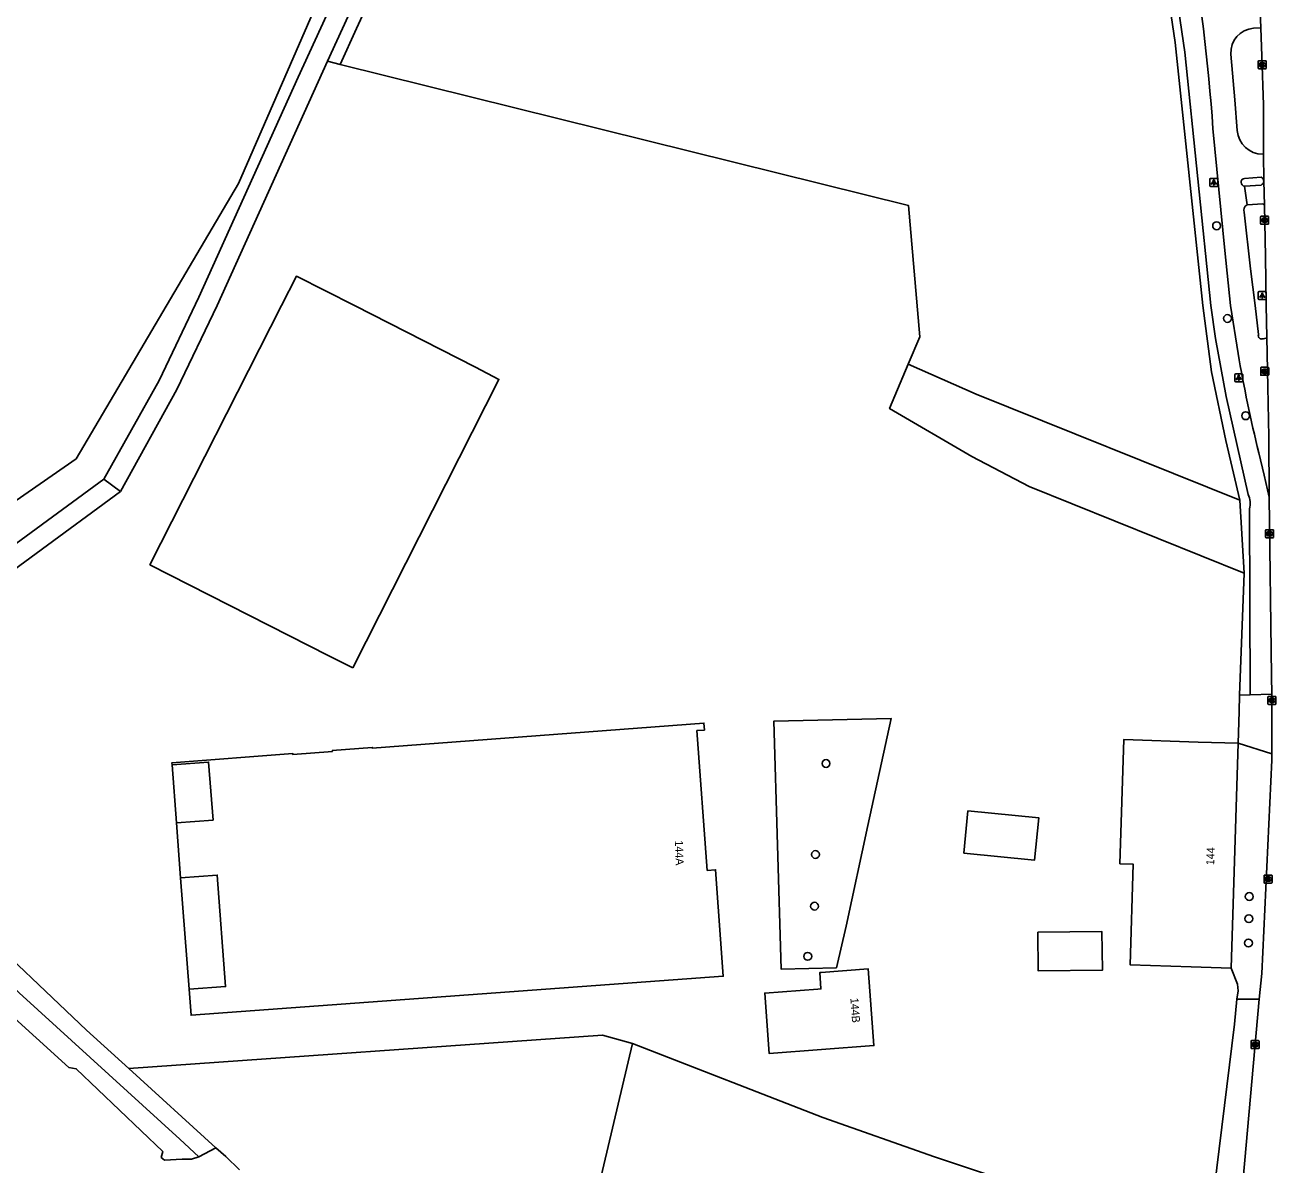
# Model space of a CAD drawing. Extents: x 160203 to 161526, y 379529 to 381797.
# Drawn here: x 160660 to 160816.2, y 380642.7 to 380785.1 of the extents above; entities that cross this region are included whole.
import ezdxf

# ---------------------------------------------------------------- set-up
doc = ezdxf.new("R2010")
doc.units = 0
for name, color, linetype in [('IMGEO_Boom', 7, 'Continuous'), ('IMGEO_Erf', 7, 'Continuous'), ('IMGEO_Grasland_agrarisch', 7, 'Continuous'), ('IMGEO_Groenvoorziening', 7, 'Continuous'), ('IMGEO_Hek', 7, 'Continuous'), ('IMGEO_Houtwal', 7, 'Continuous'), ('IMGEO_Kolk', 7, 'Continuous'), ('IMGEO_Lichtpunt', 7, 'Continuous'), ('IMGEO_Loofbos', 7, 'Continuous'), ('IMGEO_Pand', 7, 'Continuous'), ('IMGEO_Pand_nummerreeks', 7, 'Continuous'), ('IMGEO_Rijbaan_lokaal_gesloten', 7, 'Continuous'), ('IMGEO_Rijbaan_lokaal_open', 7, 'Continuous'), ('IMGEO_Voetpad_open', 7, 'Continuous')]:
    doc.layers.add(name, color=color, linetype=linetype)

msp = doc.modelspace()

# ---------------------------------------------------------------- linework, layer by layer
at = {"layer": 'IMGEO_Boom'}
for centre in [(160808.83, 380759.98), (160810.19, 380748.4), (160812.47, 380736.25), (160760.04, 380692.81), (160758.72, 380681.44), (160812.91, 380676.19), (160758.61, 380674.98), (160812.86, 380673.42), (160812.81, 380670.38), (160757.76, 380668.72)]:
    msp.add_circle(centre, 0.489, dxfattribs=at)
at = {"layer": 'IMGEO_Erf'}
for points in [[(160678.9, 380685.39), (160678.35, 380692.64)], [(160680.48, 380664.6), (160679.42, 380678.51)]]:
    msp.add_lwpolyline(points, dxfattribs=at)
at = {"layer": 'IMGEO_Grasland_agrarisch'}
for points in [[(160790.76, 380843.76), (160790.97, 380843.22), (160797.79, 380818.98), (160800.72, 380802.88), (160803.67, 380782.86), (160807.1, 380750), (160808.2, 380741.73), (160810, 380733.14), (160811.75, 380725.72)], [(160720.34, 380842.84), (160718.62, 380836.68), (160700.37, 380796.74), (160686.67, 380765.25), (160666.36, 380730.85), (160621.5, 380699.73)], [(160699.37, 380780.13), (160701.38, 380784.64), (160714.86, 380813.86), (160723.93, 380836.63), (160726.67, 380842.6)], [(160770.32, 380742.69), (160771.75, 380746.09), (160770.35, 380762.5), (160699.37, 380780.13)], [(160622.14, 380693.79), (160630.09, 380686.48), (160640.16, 380677.59), (160653.65, 380665.52), (160665.46, 380654.82), (160666.38, 380654.67), (160677.2, 380644.36), (160677, 380643.61), (160677.41, 380643.27), (160679.6, 380643.4), (160680.77, 380643.4), (160681.71, 380643.69)], [(160672.96, 380654.7), (160732.12, 380658.89), (160735.88, 380657.84)], [(160735.88, 380657.84), (160724.41, 380609.36)], [(160735.88, 380657.84), (160759.66, 380648.6), (160773.61, 380643.68), (160785.98, 380639.57), (160793.62, 380637.24), (160800.02, 380635.88), (160807.89, 380634.51)], [(160683.83, 380644.81), (160685.06, 380643.7), (160686.77, 380642.05)]]:
    msp.add_lwpolyline(points, dxfattribs=at)
at = {"layer": 'IMGEO_Groenvoorziening'}
for points in [[(160699.37, 380780.13), (160697.76, 380780.53)], [(160627.87, 380697.54), (160669.82, 380728.32)], [(160671.92, 380726.79), (160629.71, 380695.79)], [(160811.71, 380701.35), (160812.29, 380716.6)], [(160811.37, 380663.36), (160811.08, 380660.23), (160807.89, 380634.51)]]:
    msp.add_lwpolyline(points, dxfattribs=at)
at = {"layer": 'IMGEO_Hek'}
for points in [[(160724.66, 380842.65), (160726.67, 380842.6), (160727.3, 380842.58), (160755.37, 380841.81), (160764.5, 380841.73), (160790.97, 380843.22), (160797.79, 380818.98), (160800.72, 380802.88), (160803.67, 380782.86), (160807.1, 380750), (160808.2, 380741.73), (160810, 380733.14), (160811.75, 380725.72), (160812.29, 380716.6)], [(160697.76, 380780.53), (160717.43, 380823.37), (160724.66, 380842.65)], [(160671.92, 380726.79), (160669.82, 380728.32)], [(160762.54, 380672.48), (160761.33, 380667.29), (160754.45, 380667.1), (160753.51, 380698.09), (160768.19, 380698.42), (160765.28, 380685.05), (160762.54, 380672.48)]]:
    msp.add_lwpolyline(points, dxfattribs=at)
at = {"layer": 'IMGEO_Houtwal'}
for points in [[(160669.82, 380728.32), (160676.73, 380740.67), (160681.71, 380751.04), (160694.11, 380778.56), (160715.12, 380824.33), (160722.04, 380842.77)], [(160724.66, 380842.65), (160717.43, 380823.37), (160697.76, 380780.53)], [(160697.76, 380780.53), (160683.99, 380750), (160678.95, 380739.53), (160671.92, 380726.79)], [(160669.82, 380728.32), (160671.92, 380726.79)], [(160681.71, 380643.69), (160679.32, 380645.87), (160659.26, 380664.16), (160632.89, 380689.2), (160626.22, 380695.53), (160623.04, 380694.18), (160622.14, 380693.79)], [(160629.71, 380695.79), (160633.59, 380692.1), (160653.08, 380673.31), (160667.68, 380659.51), (160672.96, 380654.7)], [(160683.83, 380644.81), (160672.96, 380654.7)], [(160681.71, 380643.69), (160683.83, 380644.81)]]:
    msp.add_lwpolyline(points, dxfattribs=at)
at = {"layer": 'IMGEO_Kolk'}
for p, q in [((160814.03, 380779.66), (160814.03, 380780.51)), ((160814.1, 380780.59), (160814.95, 380780.59)), ((160815.03, 380780.51), (160815.03, 380779.66)), ((160814.95, 380779.58), (160814.1, 380779.58)), ((160814.51, 380780.36), (160814.54, 380780.36)), ((160814.54, 380779.81), (160814.51, 380779.81)), ((160814.33, 380760.25), (160814.33, 380761.1)), ((160814.4, 380761.18), (160815.26, 380761.18)), ((160815.26, 380760.18), (160814.4, 380760.18)), ((160814.84, 380760.4), (160814.81, 380760.4)), ((160814.82, 380760.96), (160814.84, 380760.96)), ((160815.33, 380761.1), (160815.33, 380760.25)), ((160814.34, 380741.37), (160814.34, 380742.22)), ((160814.41, 380742.3), (160815.26, 380742.3)), ((160814.82, 380742.08), (160814.85, 380742.08)), ((160814.85, 380741.52), (160814.82, 380741.52)), ((160815.34, 380742.22), (160815.34, 380741.37)), ((160815.26, 380741.3), (160814.41, 380741.3)), ((160814.94, 380721.08), (160814.94, 380721.93)), ((160815.02, 380722), (160815.87, 380722)), ((160815.43, 380721.78), (160815.46, 380721.78)), ((160815.45, 380721.22), (160815.43, 380721.22)), ((160815.94, 380721.93), (160815.94, 380721.08)), ((160815.87, 380721), (160815.02, 380721)), ((160815.25, 380700.27), (160815.25, 380701.12)), ((160815.32, 380701.19), (160816.18, 380701.19)), ((160815.74, 380700.97), (160815.76, 380700.97)), ((160816.25, 380701.12), (160816.25, 380700.27)), ((160816.18, 380700.19), (160815.32, 380700.19)), ((160815.76, 380700.41), (160815.73, 380700.41)), ((160814.84, 380678.87), (160815.69, 380678.87)), ((160814.77, 380677.95), (160814.77, 380678.8)), ((160815.69, 380677.87), (160814.84, 380677.87)), ((160815.25, 380678.65), (160815.28, 380678.65)), ((160815.28, 380678.09), (160815.25, 380678.09)), ((160815.77, 380678.8), (160815.77, 380677.95)), ((160813.14, 380657.27), (160813.14, 380658.13)), ((160813.22, 380658.2), (160814.07, 380658.2)), ((160814.07, 380657.2), (160813.22, 380657.2)), ((160813.63, 380657.98), (160813.65, 380657.98)), ((160813.65, 380657.42), (160813.63, 380657.42)), ((160814.14, 380658.13), (160814.14, 380657.27))]:
    msp.add_line(p, q, dxfattribs=at)
for points in [[(160814.03, 380779.66), (160814.03, 380780.51)], [(160814.1, 380780.59), (160814.95, 380780.59)], [(160815.03, 380780.51), (160815.03, 380779.66)], [(160814.95, 380779.58), (160814.1, 380779.58)], [(160814.35, 380780.28), (160814.47, 380780.28), (160814.47, 380780.13), (160814.6, 380780.28), (160814.76, 380780.28), (160814.62, 380780.13), (160814.77, 380779.88), (160814.62, 380779.88), (160814.53, 380780.05), (160814.47, 380779.98), (160814.47, 380779.88), (160814.35, 380779.88), (160814.35, 380780.28)], [(160814.33, 380760.25), (160814.33, 380761.1)], [(160814.4, 380761.18), (160815.26, 380761.18)], [(160815.26, 380760.18), (160814.4, 380760.18)], [(160814.65, 380760.88), (160814.77, 380760.88), (160814.77, 380760.72), (160814.9, 380760.88), (160815.07, 380760.88), (160814.92, 380760.73), (160815.07, 380760.48), (160814.92, 380760.48), (160814.84, 380760.64), (160814.77, 380760.57), (160814.77, 380760.48), (160814.65, 380760.48), (160814.65, 380760.88)], [(160815.33, 380761.1), (160815.33, 380760.25)], [(160814.34, 380741.37), (160814.34, 380742.22)], [(160814.41, 380742.3), (160815.26, 380742.3)], [(160814.66, 380742), (160814.78, 380742), (160814.78, 380741.85), (160814.91, 380742), (160815.07, 380742), (160814.93, 380741.85), (160815.08, 380741.6), (160814.93, 380741.6), (160814.84, 380741.76), (160814.78, 380741.69), (160814.78, 380741.6), (160814.66, 380741.6), (160814.66, 380742)], [(160815.34, 380742.22), (160815.34, 380741.37)], [(160815.26, 380741.3), (160814.41, 380741.3)], [(160814.94, 380721.08), (160814.94, 380721.93)], [(160815.02, 380722), (160815.87, 380722)], [(160815.26, 380721.7), (160815.39, 380721.7), (160815.39, 380721.55), (160815.52, 380721.7), (160815.68, 380721.7), (160815.54, 380721.55), (160815.69, 380721.3), (160815.54, 380721.3), (160815.45, 380721.47), (160815.39, 380721.4), (160815.39, 380721.3), (160815.26, 380721.3), (160815.26, 380721.7)], [(160815.94, 380721.93), (160815.94, 380721.08)], [(160815.87, 380721), (160815.02, 380721)], [(160815.25, 380700.27), (160815.25, 380701.12)], [(160815.32, 380701.19), (160816.18, 380701.19)], [(160815.57, 380700.89), (160815.69, 380700.89), (160815.69, 380700.74), (160815.82, 380700.89), (160815.99, 380700.89), (160815.84, 380700.74), (160815.99, 380700.49), (160815.84, 380700.49), (160815.76, 380700.66), (160815.69, 380700.59), (160815.69, 380700.49), (160815.57, 380700.49), (160815.57, 380700.89)], [(160816.25, 380701.12), (160816.25, 380700.27)], [(160816.18, 380700.19), (160815.32, 380700.19)], [(160814.84, 380678.87), (160815.69, 380678.87)], [(160814.77, 380677.95), (160814.77, 380678.8)], [(160815.69, 380677.87), (160814.84, 380677.87)], [(160815.09, 380678.57), (160815.21, 380678.57), (160815.21, 380678.42), (160815.34, 380678.57), (160815.5, 380678.57), (160815.36, 380678.42), (160815.51, 380678.17), (160815.36, 380678.17), (160815.27, 380678.34), (160815.21, 380678.27), (160815.21, 380678.17), (160815.09, 380678.17), (160815.09, 380678.57)], [(160815.77, 380678.8), (160815.77, 380677.95)], [(160813.14, 380657.27), (160813.14, 380658.13)], [(160813.22, 380658.2), (160814.07, 380658.2)], [(160814.07, 380657.2), (160813.22, 380657.2)], [(160813.46, 380657.9), (160813.59, 380657.9), (160813.59, 380657.75), (160813.71, 380657.9), (160813.88, 380657.9), (160813.73, 380657.75), (160813.89, 380657.5), (160813.73, 380657.5), (160813.65, 380657.67), (160813.59, 380657.6), (160813.59, 380657.5), (160813.46, 380657.5), (160813.46, 380657.9)], [(160814.14, 380658.13), (160814.14, 380657.27)]]:
    msp.add_lwpolyline(points, dxfattribs=at)
for centre, start, end in [((160814.1, 380780.51), 91.552, 178.448), ((160814.1, 380780.51), 91.552, 178.448), ((160814.95, 380780.51), 1.552, 88.448), ((160814.95, 380780.51), 1.552, 88.448), ((160814.1, 380779.66), 181.552, 268.448), ((160814.1, 380779.66), 181.552, 268.448), ((160814.95, 380779.66), 271.552, 358.448), ((160814.95, 380779.66), 271.552, 358.448), ((160814.41, 380761.1), 91.552, 178.448), ((160814.41, 380761.1), 91.552, 178.448), ((160814.41, 380760.25), 181.552, 268.448), ((160814.41, 380760.25), 181.552, 268.448), ((160815.25, 380761.1), 1.552, 88.448), ((160815.25, 380761.1), 1.552, 88.448), ((160815.25, 380760.25), 271.552, 358.448), ((160815.25, 380760.25), 271.552, 358.448), ((160814.41, 380742.22), 91.552, 178.448), ((160814.41, 380742.22), 91.552, 178.448), ((160814.41, 380741.37), 181.552, 268.448), ((160814.41, 380741.37), 181.552, 268.448), ((160815.26, 380742.22), 1.552, 88.448), ((160815.26, 380742.22), 1.552, 88.448), ((160815.26, 380741.37), 271.552, 358.448), ((160815.26, 380741.37), 271.552, 358.448), ((160815.02, 380721.93), 91.552, 178.448), ((160815.02, 380721.93), 91.552, 178.448), ((160815.02, 380721.08), 181.552, 268.448), ((160815.02, 380721.08), 181.552, 268.448), ((160815.87, 380721.93), 1.552, 88.448), ((160815.87, 380721.93), 1.552, 88.448), ((160815.87, 380721.08), 271.552, 358.448), ((160815.87, 380721.08), 271.552, 358.448), ((160815.32, 380701.12), 91.552, 178.448), ((160815.32, 380701.12), 91.552, 178.448), ((160816.17, 380701.12), 1.552, 88.448), ((160816.17, 380701.12), 1.552, 88.448), ((160815.32, 380700.27), 181.552, 268.448), ((160815.32, 380700.27), 181.552, 268.448), ((160816.17, 380700.27), 271.552, 358.448), ((160816.17, 380700.27), 271.552, 358.448), ((160814.84, 380678.8), 91.552, 178.448), ((160814.84, 380678.8), 91.552, 178.448), ((160815.69, 380678.8), 1.552, 88.448), ((160815.69, 380678.8), 1.552, 88.448), ((160814.84, 380677.95), 181.552, 268.448), ((160814.84, 380677.95), 181.552, 268.448), ((160815.69, 380677.95), 271.552, 358.448), ((160815.69, 380677.95), 271.552, 358.448), ((160813.22, 380658.13), 91.552, 178.448), ((160813.22, 380658.13), 91.552, 178.448), ((160813.22, 380657.28), 181.552, 268.448), ((160813.22, 380657.28), 181.552, 268.448), ((160814.07, 380658.13), 1.552, 88.448), ((160814.07, 380658.13), 1.552, 88.448), ((160814.07, 380657.28), 271.552, 358.448), ((160814.07, 380657.28), 271.552, 358.448)]:
    msp.add_arc(centre, 0.0765, start, end, dxfattribs=at)
for centre, major_axis, ratio, start_param, end_param in [((160814.51, 380780.08), (-0.387, 0.002), 0.722429, 4.712389, 7.853982), ((160814.54, 380780.08), (-0.39, 0.002), 0.717154, 1.570796, 4.712389), ((160814.82, 380760.68), (-0.387, 0.002), 0.722429, 4.712389, 7.853982), ((160814.84, 380760.68), (-0.39, 0.002), 0.717154, 1.570796, 4.712389), ((160814.82, 380741.8), (-0.387, 0.002), 0.722429, 4.712389, 7.853982), ((160814.85, 380741.8), (-0.39, 0.002), 0.717154, 1.570796, 4.712389), ((160815.43, 380721.5), (-0.387, 0.002), 0.722429, 4.712389, 7.853982), ((160815.45, 380721.5), (-0.39, 0.002), 0.717154, 1.570796, 4.712389), ((160815.74, 380700.69), (-0.387, 0.002), 0.722429, 4.712389, 7.853982), ((160815.76, 380700.69), (-0.39, 0.002), 0.717154, 1.570796, 4.712389), ((160815.25, 380678.37), (-0.387, 0.002), 0.722429, 4.712389, 7.853982), ((160815.28, 380678.37), (-0.39, 0.002), 0.717154, 1.570796, 4.712389), ((160813.63, 380657.7), (-0.387, 0.002), 0.722429, 4.712389, 7.853982), ((160813.65, 380657.7), (-0.39, 0.002), 0.717154, 1.570796, 4.712389)]:
    msp.add_ellipse(centre, major_axis=major_axis, ratio=ratio, start_param=start_param, end_param=end_param, dxfattribs=at)
at = {"layer": 'IMGEO_Lichtpunt'}
for p, q in [((160807.99, 380765.8), (160807.99, 380764.99)), ((160807.99, 380765.8), (160807.99, 380764.99)), ((160808.89, 380765.89), (160808.09, 380765.89)), ((160808.89, 380765.89), (160808.09, 380765.89)), ((160808.09, 380764.89), (160808.89, 380764.89)), ((160808.09, 380764.89), (160808.89, 380764.89)), ((160808.99, 380764.99), (160808.99, 380765.8)), ((160808.99, 380764.99), (160808.99, 380765.8)), ((160814.04, 380751.66), (160814.04, 380750.86)), ((160814.04, 380751.66), (160814.04, 380750.86)), ((160814.94, 380751.76), (160814.13, 380751.76)), ((160814.94, 380751.76), (160814.13, 380751.76)), ((160814.13, 380750.76), (160814.94, 380750.76)), ((160814.13, 380750.76), (160814.94, 380750.76)), ((160815.03, 380750.86), (160815.03, 380751.66)), ((160815.03, 380750.86), (160815.03, 380751.66)), ((160811.1, 380741.39), (160811.1, 380740.59)), ((160811.1, 380741.39), (160811.1, 380740.59)), ((160812.01, 380741.49), (160811.2, 380741.49)), ((160812.01, 380741.49), (160811.2, 380741.49)), ((160812.1, 380740.59), (160812.1, 380741.39)), ((160812.1, 380740.59), (160812.1, 380741.39)), ((160811.2, 380740.49), (160812.01, 380740.49)), ((160811.2, 380740.49), (160812.01, 380740.49))]:
    msp.add_line(p, q, dxfattribs=at)
for points in [[(160808.37, 380765.46), (160808.4, 380765.43), (160808.22, 380765.17), (160808.18, 380765.2), (160808.37, 380765.46)], [(160808.47, 380765.41), (160808.52, 380765.41), (160808.52, 380765.09), (160808.47, 380765.09), (160808.47, 380765.41)], [(160808.58, 380765.43), (160808.62, 380765.46), (160808.8, 380765.2), (160808.76, 380765.17), (160808.58, 380765.43)], [(160814.41, 380751.33), (160814.45, 380751.3), (160814.26, 380751.04), (160814.22, 380751.07), (160814.41, 380751.33)], [(160814.51, 380751.28), (160814.56, 380751.28), (160814.56, 380750.96), (160814.51, 380750.96), (160814.51, 380751.28)], [(160814.62, 380751.3), (160814.66, 380751.33), (160814.85, 380751.06), (160814.81, 380751.04), (160814.62, 380751.3)], [(160811.48, 380741.06), (160811.52, 380741.03), (160811.33, 380740.77), (160811.29, 380740.79), (160811.48, 380741.06)], [(160811.58, 380741.01), (160811.63, 380741.01), (160811.63, 380740.69), (160811.58, 380740.69), (160811.58, 380741.01)], [(160811.69, 380741.03), (160811.73, 380741.06), (160811.92, 380740.79), (160811.88, 380740.77), (160811.69, 380741.03)]]:
    msp.add_lwpolyline(points, dxfattribs=at)
for centre in [(160808.49, 380765.59), (160814.54, 380751.46), (160811.6, 380741.19)]:
    msp.add_circle(centre, 0.0994, dxfattribs=at)
for centre, start, end in [((160808.09, 380765.8), 90, 180), ((160808.09, 380765.8), 90, 180), ((160808.09, 380764.99), 180, 270), ((160808.09, 380764.99), 180, 270), ((160808.89, 380765.8), 0, 90), ((160808.89, 380765.8), 0, 90), ((160808.89, 380764.99), 270, 0), ((160808.89, 380764.99), 270, 360), ((160814.13, 380751.66), 90, 180), ((160814.13, 380751.66), 90, 180), ((160814.13, 380750.86), 180, 270), ((160814.13, 380750.86), 180, 270), ((160814.94, 380751.66), 0, 90), ((160814.94, 380751.66), 0, 90), ((160814.94, 380750.86), 270, 0), ((160814.94, 380750.86), 270, 360), ((160811.2, 380741.39), 90, 180), ((160811.2, 380741.39), 90, 180), ((160812.01, 380741.39), 0, 90), ((160812.01, 380741.39), 0, 90), ((160811.2, 380740.59), 180, 270), ((160811.2, 380740.59), 180, 270), ((160812.01, 380740.59), 270, 0), ((160812.01, 380740.59), 270, 360)]:
    msp.add_arc(centre, 0.0946, start, end, dxfattribs=at)
at = {"layer": 'IMGEO_Loofbos'}
for points in [[(160812.29, 380716.6), (160785.41, 380727.43), (160778.24, 380731.15), (160767.99, 380737.14), (160770.32, 380742.69)], [(160811.75, 380725.72), (160778.78, 380738.94), (160770.32, 380742.69)], [(160812.29, 380716.6), (160811.75, 380725.72)]]:
    msp.add_lwpolyline(points, dxfattribs=at)
at = {"layer": 'IMGEO_Pand'}
for points in [[(160700.92, 380704.77), (160697.93, 380706.25), (160675.59, 380717.63), (160692.02, 380750), (160693.89, 380753.68), (160701.12, 380750), (160716.24, 380742.3), (160719.19, 380740.79), (160700.92, 380704.77)], [(160678.35, 380692.64), (160678.33, 380692.9), (160693.44, 380694.04), (160693.45, 380693.92), (160698.39, 380694.29), (160698.37, 380694.45), (160703.36, 380694.82), (160703.36, 380694.71), (160744.79, 380697.86), (160744.86, 380696.99), (160743.92, 380696.92), (160745.2, 380679.45), (160746.24, 380679.53), (160747.21, 380666.23), (160680.72, 380661.37), (160680.48, 380664.6)], [(160810.64, 380667.26), (160805.64, 380667.42), (160798.02, 380667.66), (160798.41, 380680.23), (160796.76, 380680.28), (160797.24, 380695.79), (160806.52, 380695.49), (160811.52, 380695.34)], [(160811.52, 380695.34), (160810.64, 380667.26)], [(160678.35, 380692.64), (160682.92, 380692.99), (160683.47, 380685.74), (160678.9, 380685.39)], [(160777.25, 380681.59), (160786.1, 380680.74), (160786.61, 380686.04), (160777.76, 380686.89), (160777.25, 380681.59)], [(160679.42, 380678.51), (160678.9, 380685.39)], [(160679.42, 380678.51), (160683.99, 380678.86), (160685.04, 380664.95), (160680.48, 380664.6)], [(160786.5, 380671.73), (160794.51, 380671.81), (160794.56, 380666.98), (160786.53, 380666.93), (160786.5, 380671.73)], [(160765.52, 380664.39), (160765.32, 380667.14), (160759.43, 380666.7), (160759.26, 380666.69), (160759.41, 380664.66), (160759.02, 380664.63), (160752.38, 380664.14), (160752.93, 380656.6), (160766.03, 380657.57), (160765.52, 380664.39)]]:
    msp.add_lwpolyline(points, dxfattribs=at)
at = {"layer": 'IMGEO_Rijbaan_lokaal_gesloten'}
for points in [[(160814.24, 380787.76), (160814.36, 380784.69)], [(160814.36, 380784.69), (160814.5, 380781.17), (160814.67, 380775.07), (160814.71, 380769.22), (160814.71, 380768.94)], [(160814.71, 380768.94), (160814.73, 380765.58)], [(160814.73, 380765.58), (160814.8, 380762.51)], [(160814.8, 380762.51), (160814.92, 380756.15), (160815.04, 380750), (160815.12, 380746.06)], [(160815.12, 380746.06), (160815.24, 380739.84), (160815.35, 380733.62), (160815.39, 380726.08)], [(160815.39, 380726.08), (160815.69, 380703.75), (160815.73, 380701.45)], [(160815.73, 380701.45), (160815.75, 380700.69), (160815.75, 380694.01)], [(160815.75, 380694.01), (160815.75, 380693.24), (160814.47, 380666.58), (160814.16, 380663.37)], [(160814.16, 380663.37), (160810, 380616.63), (160807.06, 380582.56), (160806.42, 380576.04)]]:
    msp.add_lwpolyline(points, dxfattribs=at)
at = {"layer": 'IMGEO_Rijbaan_lokaal_open'}
for points in [[(160814.36, 380784.69), (160813.44, 380784.65)], [(160810.6, 380781.42), (160811.09, 380775.73), (160811.42, 380771.88)], [(160811.51, 380744.02), (160810.58, 380750), (160809.84, 380756.9), (160808.37, 380772.11)], [(160814.61, 380768.92), (160814.71, 380768.94)], [(160814.39, 380766.07), (160812.3, 380765.9)], [(160812.33, 380764.93), (160812.63, 380762.58)], [(160812.28, 380761.66), (160813.07, 380754.58), (160813.63, 380750), (160814.07, 380746.41)], [(160815.39, 380726.08), (160814.76, 380728.84), (160814.09, 380731.63)]]:
    msp.add_lwpolyline(points, dxfattribs=at)
for centre, radius, start, end in [((160559.15, 380754.68), 249.83, 3.9986, 9.7428), ((160813.65, 380781.6), 3.05, 93.8042, 183.3379), ((160814.59, 380772.1), 3.18, 184.1055, 270.3119), ((160812.38, 380765.41), 0.489, 99.7815, 264.0013), ((160814.11, 380765.51), 0.62, 5.871, 63.7848), ((160812.95, 380761.93), 0.719, 116.2822, 202.2637), ((160814.46, 380746.25), 0.418, 158.1843, 272.3215), ((160814.56, 380746.63), 0.793, 264.1823, 314.6696), ((161012.53, 380779.56), 204.14, 190.0259, 193.5779)]:
    msp.add_arc(centre, radius, start, end, dxfattribs=at)
at = {"layer": 'IMGEO_Voetpad_open'}
for points in [[(160801.95, 380801.49), (160804.88, 380781.65), (160808.1, 380750), (160808.68, 380745.88), (160810.03, 380738.64), (160812.76, 380726.41)], [(160812.33, 380764.93), (160814.39, 380765.07)], [(160814.8, 380762.51), (160814.61, 380762.72), (160812.63, 380762.58)], [(160812.94, 380724.63), (160813.03, 380701.39)], [(160811.71, 380701.35), (160811.63, 380699.29), (160811.52, 380695.34)], [(160813.03, 380701.39), (160811.71, 380701.35)], [(160815.73, 380701.45), (160813.03, 380701.39)], [(160811.52, 380695.34), (160815.75, 380694.01)], [(160810.64, 380667.26), (160811.46, 380665.26), (160811.54, 380664.41), (160811.37, 380663.36)], [(160814.16, 380663.37), (160811.37, 380663.36)]]:
    msp.add_lwpolyline(points, dxfattribs=at)
for centre, radius, start, end in [((160814.13, 380765.61), 0.6, 295.455, 356.8013), ((160810.38, 380725.27), 2.64, 345.7972, 25.4327)]:
    msp.add_arc(centre, radius, start, end, dxfattribs=at)

# ---------------------------------------------------------------- texts
at = {"layer": 'IMGEO_Pand_nummerreeks'}
for s, rotation, p in [('144A', 272.1465, (160741.16, 380683.19)), ('144', 88.2006, (160808.52, 380680.09)), ('144B', 274.2282, (160763.08, 380663.5))]:
    msp.add_text(s, height=1, rotation=rotation, dxfattribs=at).set_placement(p)

doc.saveas('drawing.dxf')
